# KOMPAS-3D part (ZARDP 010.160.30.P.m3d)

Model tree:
1. Плоскость XY
2. Плоскость ZX
3. Плоскость ZY
4. Ось X
5. Ось Y
6. Ось Z
7. Начало координат
8. Смещенная плоскость:2
     Расстояние = 57.5
9. Смещенная плоскость:3
     Расстояние = 85
10. Смещенная плоскость:4
     Расстояние = 85
11. Булева операция:1
12. Булева операция:2
13. Булева операция:3
14. Булева операция:4
15. Булева операция:7
16. Булева операция:8
